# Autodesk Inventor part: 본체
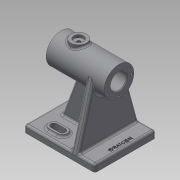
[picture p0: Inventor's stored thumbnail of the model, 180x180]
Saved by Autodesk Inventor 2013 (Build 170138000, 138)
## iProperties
Created: 2019-10
Part Number: 본체
Material: 일반
Document SubType Name: Modeling
Designer: Administrator
Density: 1 g/cm^3
Author: Administrator
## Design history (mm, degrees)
sketch "스케치1"
  geometry: C1 r 21 at (0, 0); 1 further point
  constraints: 1 centre point, 1 coincident
  dimensions: "d0" = 42 diameter of C1
extrude "돌출1" new body sketch "스케치1" stored distance "d1" = 82; taper "d2" = 0 deg
hole "구멍1" diameter "d5" = 23; stored, may be unused: countersink angle "d9" = 90 deg, drill point angle "d11" = 118 deg; dims "d3" = 10, "d4" = 10, "d6" = 6, "d7" = 29, "d8" = 62, "d10" = 8
sketch "스케치2"
  geometry: C1 r 14.5 at (0, 0) reference; 1 further point
  constraints: 1 vertical alignment
  dimensions: "d12" = 18 distance of C1.centre point (0, 18)
hole "구멍2" sketch "스케치2" at (0, 18) diameter "d13" = 2.459; stored, may be unused: countersink angle "d17" = 90 deg, drill point angle "d19" = 118 deg; dims "d14" = 8, "d15" = 29, "d16" = 62, "d18" = 10
node "작업 평면1"
sketch "스케치3"
  geometry: L1 (21, 41)-(-21, 41) reference; C1 r 11 at (0, 16); 1 further point
  constraints: 1 centre point, 1 vertical alignment
  dimensions: "d24" = 25 distance from line of L1 C1.centre; "d25" = 22 diameter of C1
extrude "돌출2" join sketch "스케치3" stored distance "d26" = 82; taper "d27" = 0 deg
sketch "스케치4"
  geometry: C1 r 11 at (0, 0) reference; C2 r 7 at (0, 0); 1 further point
  constraints: 1 centre point, 1 coincident
  dimensions: "d28" = 14 diameter of C2
extrude "돌출3" cut sketch "스케치4" distance "d30" = 4; taper "d31" = 0 deg
hole "구멍3" diameter "d34" = 4.917; stored, may be unused: countersink angle "d38" = 90 deg, drill point angle "d40" = 0 deg; dims "d32" = 10, "d33" = 10, "d35" = 8, "d36" = 29, "d37" = 62, "d39" = 10
sketch "스케치5"
  geometry: L1 (-76, -50)-(-86, -50); L2 (-86, -50)-(-86, 50); L3 (-86, 50)-(-76, 50); L4 (-76, 50)-(-76, -50); 2 further points
  constraints: 8 end point, 2 parallel, 1 horizontal, 1 horizontal alignment, 1 midpoint, 1 perpendicular
  dimensions: "d41" = 100 distance of L1.end L2.end; "d43" = 10 distance of L1.start L1.end; "d44" = 86 distance from line of point (0, 0) L2
extrude "돌출4" join sketch "스케치5" stored distance "d45" = 86; taper "d46" = 0 deg
sketch "스케치6"
  geometry: L1 (86, 0)-(0, 0) reference; L2 (86, 100)-(86, 0) reference; L3 (9, 26)-(9, 38); L4 (23, 26)-(23, 38); L5 (11.5, 26)-(11.5, 38); L6 (20.5, 26)-(20.5, 38); A1 r 7 centre (16, 26) between (9, 26) and (23, 26); A2 r 7 centre (16, 38) between (23, 38) and (9, 38); A3 r 4.5 centre (16, 26) between (11.5, 26) and (20.5, 26); A4 r 4.5 centre (16, 38) between (20.5, 38) and (11.5, 38); 1 further point
  constraints: 8 end point, 8 point on circle, 7 tangent, 4 centre point, 2 coincident, 2 equal radius, 1 parallel, 1 vertical alignment
  dimensions: "d49" = 12 distance of L3.start L3.end; "d50" = 14 distance between parallel lines of L4 L3; "d51" = 27 horizontal distance of point (43, 50) A2.centre; "d52" = 26 distance from line of L1 A1.centre; "d53" = 9 distance between parallel lines of L6 L5
extrude "돌출5" join sketch "스케치6" distance "d54" = 3; taper "d55" = 0 deg
sketch "스케치7"
  geometry: L1 (-4.5, 12)-(-4.5, 0) reference; L2 (4.5, 0)-(4.5, 12) reference; A1 r 4.5 centre (0, 0) between (-4.5, 0) and (4.5, 0) reference; A2 r 4.5 centre (0, 12) between (4.5, 12) and (-4.5, 12) reference; 1 further point
extrude "돌출6" cut sketch "스케치7" stored distance "d56" = 3; taper "d57" = 0 deg
node "작업 평면2"
fillet "모깎기7" dims "d84" = 3
fillet "모깎기8" dims "d85" = 3
node "작업 평면3"
sketch "스케치14"
  geometry: L1 (-20.272, 5.48)-(-42.896, -78.217); L2 (20.272, 5.48)-(42.896, -78.217); L3 (-40, -76)-(40, -76) reference; A1 r 21 centre (0, 0) between (-20.272, 5.48) and (20.272, 5.48) reference; A2 r 3 centre (-40, -79) between (-40, -76) and (-43, -79) reference; A3 r 3 centre (40, -79) between (43, -79) and (40, -76) reference; 1 further point
  constraints: 4 end point, 4 point on circle, 4 tangent
extrude "돌출8" join sketch "스케치14" distance "d87" = 10; taper "d88" = 0 deg
sketch "스케치15"
  geometry: L1 (-76, 47)-(-76, -47) reference; L2 (-76, 35)-(-65.7, 31.251); L3 (-86, 50)-(-79, 50) reference; 2 further points
  constraints: 2 end point, 1 point on line
  dimensions: "d89" = 70 deg angle of L1 L2; "d90" = 15 distance from line of L3 L2.start
feature "리브2" sketch "스케치15" dims "d91" = 1, "d92" = 10, "d93" = 0, "d94" = 0, "d95" = 1, "d96" = 1
sketch "스케치16"
  geometry: L1 (80, 3)-(0, 3) reference; 4 further points
  constraints: 1 vertical alignment, 1 other
  dimensions: "d99" = 7 distance from line of L1 point (40, -4)
feature "엠보싱2" sketch "스케치16" dims "d100" = 0.5, "d101" = 0
fillet "모깎기11" dims "d102" = 3
fillet "모깎기12" dims "d103" = 3
chamfer "모따기2" distance "d104" = 1; stored, may be unused: second distance "d105" = 2, angle "d106" = 45 deg
node "솔리드1"
pattern_circular "원형 패턴1" dims angle "d21" = 360 deg
mirror "대칭1"
mirror "대칭2"
other parameters: "d23" = 24, "d60" = -26, "d86" = -26
